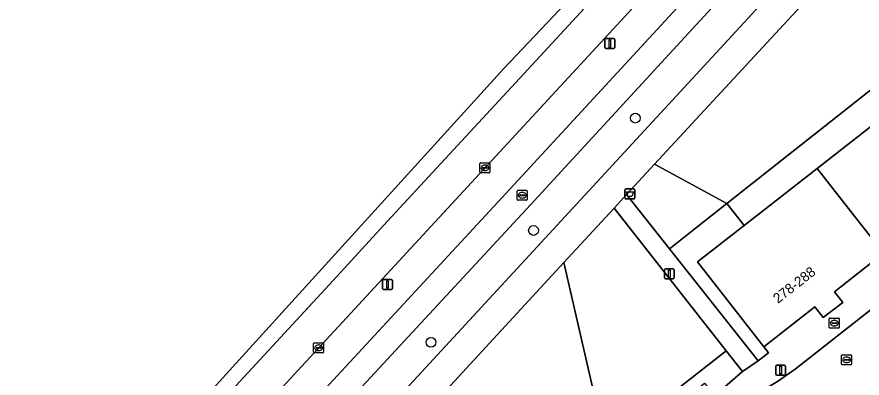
# Model space of a CAD drawing. Extents: x 159217 to 160349, y 381246 to 382172.
# Drawn here: x 159660.9 to 159745.5, y 381709.6 to 381745.8 of the extents above; entities that cross this region are included whole.
import ezdxf

# ---------------------------------------------------------------- set-up
doc = ezdxf.new("R2010")
doc.units = 0
for name, color, linetype in [('IMGEO_Afvalbak', 7, 'Continuous'), ('IMGEO_Berm_groen', 7, 'Continuous'), ('IMGEO_Boom', 7, 'Continuous'), ('IMGEO_Brandkraan', 7, 'Continuous'), ('IMGEO_Fietspad_gesloten', 7, 'Continuous'), ('IMGEO_Groenvoorziening', 7, 'Continuous'), ('IMGEO_Haag', 7, 'Continuous'), ('IMGEO_Kolk', 7, 'Continuous'), ('IMGEO_Lichtmast', 7, 'Continuous'), ('IMGEO_Pand', 7, 'Continuous'), ('IMGEO_Pand_nummerreeks', 7, 'Continuous'), ('IMGEO_Rijbaan_lokaal_open', 7, 'Continuous'), ('IMGEO_Rijbaan_regionaal_gesloten', 7, 'Continuous'), ('IMGEO_Rioolput', 7, 'Continuous'), ('IMGEO_Voetpad_open', 7, 'Continuous')]:
    doc.layers.add(name, color=color, linetype=linetype)

msp = doc.modelspace()

# ---------------------------------------------------------------- linework, layer by layer
at = {"layer": 'IMGEO_Afvalbak'}
for p, q in [((159721.722, 381727.669), (159721.722, 381728.469)), ((159721.722, 381728.469), (159721.722, 381727.669)), ((159721.822, 381728.569), (159722.612, 381728.569)), ((159722.612, 381728.569), (159721.822, 381728.569)), ((159722.712, 381728.469), (159722.712, 381727.669)), ((159722.712, 381727.669), (159722.712, 381728.469)), ((159722.612, 381727.569), (159721.822, 381727.569)), ((159721.822, 381727.569), (159722.612, 381727.569))]:
    msp.add_line(p, q, dxfattribs=at)
msp.add_lwpolyline([(159721.865, 381728.283), (159722.569, 381728.283), (159722.42, 381727.813), (159722.014, 381727.813), (159721.865, 381728.283)], dxfattribs=at)
for centre, start, end in [((159721.822, 381728.469), 90, 180), ((159721.822, 381728.469), 90, 180), ((159722.612, 381728.469), 0, 90), ((159722.612, 381728.469), 360, 90), ((159721.822, 381727.669), 180, 270), ((159721.822, 381727.669), 180, 270), ((159722.612, 381727.669), 270, 0), ((159722.612, 381727.669), 270, 0)]:
    msp.add_arc(centre, 0.1, start, end, dxfattribs=at)
at = {"layer": 'IMGEO_Berm_groen'}
msp.add_lwpolyline([(159853.494, 381886.181), (159852.47, 381885.258), (159842.203, 381875.059), (159835.047, 381867.74), (159825.175, 381857.422), (159808.382, 381839.524), (159762.299, 381789.78), (159757.702, 381784.817), (159640.048, 381657.48), (159637.399, 381654.559), (159636.301, 381652.991), (159629.478, 381641.885), (159628.555, 381640.744), (159629.543, 381639.855), (159629.68, 381639.699), (159634.406, 381645.8), (159639.364, 381651.824), (159643.967, 381657.085), (159662.078, 381676.527), (159710.236, 381728.578), (159764.638, 381787.591)], dxfattribs=at)
at = {"layer": 'IMGEO_Boom'}
for centre in [(159722.763, 381735.66), (159712.574, 381724.417), (159702.303, 381713.224)]:
    msp.add_circle(centre, 0.489, dxfattribs=at)
at = {"layer": 'IMGEO_Brandkraan'}
for p, q in [((159742.178, 381714.715), (159742.178, 381715.567)), ((159742.253, 381715.641), (159743.105, 381715.641)), ((159742.666, 381715.421), (159742.691, 381715.421)), ((159743.179, 381715.567), (159743.179, 381714.715)), ((159743.105, 381714.641), (159742.253, 381714.641)), ((159742.437, 381715.135), (159742.437, 381715.147)), ((159742.875, 381715.098), (159742.477, 381715.098)), ((159742.48, 381715.184), (159742.878, 381715.184)), ((159742.689, 381714.861), (159742.664, 381714.861)), ((159742.921, 381715.147), (159742.921, 381715.135))]:
    msp.add_line(p, q, dxfattribs=at)
for points in [[(159742.178, 381714.715), (159742.178, 381715.567)], [(159742.253, 381715.641), (159743.105, 381715.641)], [(159743.179, 381715.567), (159743.179, 381714.715)], [(159743.105, 381714.641), (159742.253, 381714.641)]]:
    msp.add_lwpolyline(points, dxfattribs=at)
for centre, radius, start, end in [((159742.255, 381715.565), 0.0765, 91.55205, 178.44795), ((159742.255, 381715.565), 0.0765, 91.55205, 178.44795), ((159743.103, 381715.565), 0.0765, 1.55205, 88.44795), ((159743.103, 381715.565), 0.0765, 1.55205, 88.44795), ((159742.255, 381714.717), 0.0765, 181.55205, 268.44795), ((159742.255, 381714.717), 0.0765, 181.55205, 268.44795), ((159742.477, 381715.144), 0.0403, 85.87752, 175.75265), ((159742.474, 381715.134), 0.0366, 178.93798, 274.71019), ((159742.878, 381715.141), 0.043, 264.86636, 352.45326), ((159742.882, 381715.146), 0.0386, 1.73085, 96.63898), ((159743.103, 381714.717), 0.0765, 271.55205, 358.44795), ((159743.103, 381714.717), 0.0765, 271.55205, 358.44795)]:
    msp.add_arc(centre, radius, start, end, dxfattribs=at)
for centre, major_axis, ratio, start_param, end_param in [((159742.665, 381715.141), (-0.387, 0.002), 0.722429, 4.712389, 7.853982), ((159742.69, 381715.141), (-0.39, 0.002), 0.717154, 1.570796, 4.712389)]:
    msp.add_ellipse(centre, major_axis=major_axis, ratio=ratio, start_param=start_param, end_param=end_param, dxfattribs=at)
at = {"layer": 'IMGEO_Fietspad_gesloten'}
for points in [[(159712.278, 381726.997), (159749.294, 381767.255), (159766.48, 381785.868), (159764.638, 381787.591), (159710.236, 381728.578), (159662.078, 381676.527), (159643.967, 381657.085), (159639.364, 381651.824), (159634.406, 381645.8), (159629.68, 381639.699), (159613.744, 381622.115), (159607.679, 381616.725)], [(159600.194, 381609.412), (159602.096, 381607.781), (159605.72, 381611.514), (159609.864, 381615.275), (159613.837, 381619.072), (159627.95, 381634.279), (159632.567, 381639.362), (159637.494, 381645.52), (159642.695, 381651.795), (159649.844, 381659.632), (159712.278, 381726.997)]]:
    msp.add_lwpolyline(points, dxfattribs=at)
at = {"layer": 'IMGEO_Groenvoorziening'}
for points in [[(159738.017, 381750), (159768.968, 381783.54), (159766.874, 381785.5), (159766.48, 381785.868), (159749.294, 381767.255), (159712.278, 381726.997), (159649.844, 381659.632), (159642.695, 381651.795), (159637.494, 381645.52), (159632.567, 381639.362), (159627.95, 381634.279), (159629.643, 381632.69), (159653.897, 381658.843)], [(159731.935, 381727.131), (159760.899, 381750), (159770.053, 381757.228), (159766.379, 381776.207), (159742.186, 381750), (159724.688, 381731.045)], [(159770.053, 381757.228), (159760.899, 381750), (159731.935, 381727.131), (159733.665, 381724.918), (159740.974, 381730.631), (159752.784, 381739.863), (159764.59, 381749.091), (159765.753, 381750), (159774.065, 381756.497)], [(159726.192, 381722.565), (159731.935, 381727.131), (159724.688, 381731.045), (159721.887, 381728.002)], [(159731.871, 381712.36), (159720.635, 381726.662), (159715.613, 381721.211), (159719.818, 381702.922)], [(159726.192, 381722.565), (159735.063, 381711.362), (159736.098, 381712.17), (159735.632, 381712.764), (159728.993, 381721.266), (159733.665, 381724.918), (159731.935, 381727.131)], [(159719.818, 381702.922), (159715.613, 381721.211), (159674.596, 381676.692), (159680.577, 381672.195)], [(159719.818, 381702.922), (159720.432, 381700.252), (159682.88, 381670.464), (159680.577, 381672.195), (159675.736, 381668.404), (159684.834, 381656.905), (159685.759, 381657.626), (159685.188, 381658.413), (159678.59, 381666.838), (159690.401, 381676.084), (159702.212, 381685.331), (159714.024, 381694.577), (159726.022, 381703.97), (159727.091, 381704.807), (159725.977, 381706.23), (159729.692, 381709.139), (159730.684, 381707.872), (159733.499, 381710.288), (159731.871, 381712.36)]]:
    msp.add_lwpolyline(points, close=True, dxfattribs=at)
at = {"layer": 'IMGEO_Haag'}
for points in [[(159768.968, 381783.54), (159766.874, 381785.5), (159766.48, 381785.868), (159749.294, 381767.255), (159712.278, 381726.997), (159649.844, 381659.632), (159642.695, 381651.795), (159637.494, 381645.52), (159632.567, 381639.362), (159627.95, 381634.279), (159629.643, 381632.69), (159653.897, 381658.843), (159738.017, 381750)], [(159726.192, 381722.565), (159735.063, 381711.362), (159736.098, 381712.17), (159735.632, 381712.764), (159728.993, 381721.266), (159733.665, 381724.918), (159731.935, 381727.131)], [(159719.818, 381702.922), (159720.432, 381700.252), (159682.88, 381670.464), (159680.577, 381672.195), (159675.736, 381668.404), (159684.834, 381656.905), (159685.759, 381657.626), (159685.188, 381658.413), (159678.59, 381666.838), (159690.401, 381676.084), (159702.212, 381685.331), (159714.024, 381694.577), (159726.022, 381703.97), (159727.091, 381704.807), (159725.977, 381706.23), (159729.692, 381709.139), (159730.684, 381707.872), (159733.499, 381710.288), (159731.871, 381712.36)]]:
    msp.add_lwpolyline(points, close=True, dxfattribs=at)
at = {"layer": 'IMGEO_Kolk'}
for p, q in [((159707.206, 381730.258), (159707.206, 381731.11)), ((159707.281, 381731.184), (159708.133, 381731.184)), ((159707.465, 381730.678), (159707.465, 381730.69)), ((159707.903, 381730.641), (159707.505, 381730.641)), ((159707.508, 381730.727), (159707.906, 381730.727)), ((159707.694, 381730.964), (159707.719, 381730.964)), ((159707.949, 381730.69), (159707.949, 381730.678)), ((159708.207, 381731.11), (159708.207, 381730.258)), ((159708.133, 381730.184), (159707.281, 381730.184)), ((159707.717, 381730.404), (159707.692, 381730.404)), ((159690.561, 381712.245), (159690.561, 381713.097)), ((159690.636, 381713.171), (159691.488, 381713.171)), ((159691.049, 381712.951), (159691.074, 381712.951)), ((159691.562, 381713.097), (159691.562, 381712.245)), ((159691.488, 381712.171), (159690.636, 381712.171)), ((159690.82, 381712.665), (159690.82, 381712.677)), ((159691.258, 381712.628), (159690.86, 381712.628)), ((159690.863, 381712.714), (159691.261, 381712.714)), ((159691.072, 381712.391), (159691.047, 381712.391)), ((159691.304, 381712.677), (159691.304, 381712.665))]:
    msp.add_line(p, q, dxfattribs=at)
for points in [[(159707.206, 381730.258), (159707.206, 381731.11)], [(159707.281, 381731.184), (159708.133, 381731.184)], [(159708.207, 381731.11), (159708.207, 381730.258)], [(159708.133, 381730.184), (159707.281, 381730.184)], [(159690.561, 381712.245), (159690.561, 381713.097)], [(159690.636, 381713.171), (159691.488, 381713.171)], [(159691.562, 381713.097), (159691.562, 381712.245)], [(159691.488, 381712.171), (159690.636, 381712.171)]]:
    msp.add_lwpolyline(points, dxfattribs=at)
for centre, radius, start, end in [((159707.283, 381731.108), 0.0765, 91.55205, 178.44795), ((159707.283, 381731.108), 0.0765, 91.55205, 178.44795), ((159707.505, 381730.687), 0.0403, 85.87752, 175.75265), ((159707.502, 381730.677), 0.0366, 178.93798, 274.71019), ((159707.906, 381730.684), 0.043, 264.86636, 352.45326), ((159707.91, 381730.689), 0.0386, 1.73085, 96.63898), ((159708.131, 381731.108), 0.0765, 1.55205, 88.44795), ((159708.131, 381731.108), 0.0765, 1.55205, 88.44795), ((159707.283, 381730.26), 0.0765, 181.55205, 268.44795), ((159707.283, 381730.26), 0.0765, 181.55205, 268.44795), ((159708.131, 381730.26), 0.0765, 271.55205, 358.44795), ((159708.131, 381730.26), 0.0765, 271.55205, 358.44795), ((159690.638, 381713.095), 0.0765, 91.55205, 178.44795), ((159690.638, 381713.095), 0.0765, 91.55205, 178.44795), ((159691.486, 381713.095), 0.0765, 1.55205, 88.44795), ((159691.486, 381713.095), 0.0765, 1.55205, 88.44795), ((159690.638, 381712.247), 0.0765, 181.55205, 268.44795), ((159690.638, 381712.247), 0.0765, 181.55205, 268.44795), ((159690.86, 381712.674), 0.0403, 85.87752, 175.75265), ((159690.857, 381712.664), 0.0366, 178.93798, 274.71019), ((159691.261, 381712.671), 0.043, 264.86636, 352.45326), ((159691.265, 381712.676), 0.0386, 1.73085, 96.63898), ((159691.486, 381712.247), 0.0765, 271.55205, 358.44795), ((159691.486, 381712.247), 0.0765, 271.55205, 358.44795)]:
    msp.add_arc(centre, radius, start, end, dxfattribs=at)
for centre, major_axis, ratio, start_param, end_param in [((159707.693, 381730.684), (-0.387, 0.002), 0.722429, 4.712389, 7.853982), ((159707.718, 381730.684), (-0.39, 0.002), 0.717154, 1.570796, 4.712389), ((159691.048, 381712.671), (-0.387, 0.002), 0.722429, 4.712389, 7.853982), ((159691.073, 381712.671), (-0.39, 0.002), 0.717154, 1.570796, 4.712389)]:
    msp.add_ellipse(centre, major_axis=major_axis, ratio=ratio, start_param=start_param, end_param=end_param, dxfattribs=at)
at = {"layer": 'IMGEO_Lichtmast'}
for p, q in [((159719.722, 381742.723), (159719.722, 381743.523)), ((159719.722, 381743.523), (159719.722, 381742.723)), ((159719.822, 381743.623), (159720.612, 381743.623)), ((159720.612, 381743.623), (159719.822, 381743.623)), ((159720.712, 381743.523), (159720.712, 381742.723)), ((159720.712, 381742.723), (159720.712, 381743.523)), ((159720.612, 381742.623), (159719.822, 381742.623)), ((159719.822, 381742.623), (159720.612, 381742.623)), ((159725.774, 381720.572), (159726.564, 381720.572)), ((159726.564, 381720.572), (159725.774, 381720.572)), ((159725.674, 381719.672), (159725.674, 381720.472)), ((159725.674, 381720.472), (159725.674, 381719.672)), ((159726.664, 381720.472), (159726.664, 381719.672)), ((159726.664, 381719.672), (159726.664, 381720.472)), ((159697.461, 381718.615), (159697.461, 381719.415)), ((159697.461, 381719.415), (159697.461, 381718.615)), ((159697.561, 381719.515), (159698.351, 381719.515)), ((159698.351, 381719.515), (159697.561, 381719.515)), ((159698.451, 381719.415), (159698.451, 381718.615)), ((159698.451, 381718.615), (159698.451, 381719.415)), ((159726.564, 381719.572), (159725.774, 381719.572)), ((159725.774, 381719.572), (159726.564, 381719.572)), ((159698.351, 381718.515), (159697.561, 381718.515)), ((159697.561, 381718.515), (159698.351, 381718.515)), ((159736.817, 381710.042), (159736.817, 381710.842)), ((159736.817, 381710.842), (159736.817, 381710.042)), ((159736.917, 381710.942), (159737.707, 381710.942)), ((159737.707, 381710.942), (159736.917, 381710.942)), ((159737.807, 381710.842), (159737.807, 381710.042)), ((159737.807, 381710.042), (159737.807, 381710.842)), ((159737.707, 381709.942), (159736.917, 381709.942)), ((159736.917, 381709.942), (159737.707, 381709.942))]:
    msp.add_line(p, q, dxfattribs=at)
for points in [[(159720.142, 381743.498), (159720.292, 381743.498), (159720.292, 381742.748), (159720.142, 381742.748), (159720.142, 381743.498)], [(159726.094, 381720.447), (159726.244, 381720.447), (159726.244, 381719.697), (159726.094, 381719.697), (159726.094, 381720.447)], [(159697.881, 381719.39), (159698.031, 381719.39), (159698.031, 381718.64), (159697.881, 381718.64), (159697.881, 381719.39)], [(159737.237, 381710.817), (159737.387, 381710.817), (159737.387, 381710.067), (159737.237, 381710.067), (159737.237, 381710.817)]]:
    msp.add_lwpolyline(points, dxfattribs=at)
for centre, start, end in [((159719.822, 381743.523), 90, 180), ((159719.822, 381743.523), 90, 180), ((159720.612, 381743.523), 0, 90), ((159720.612, 381743.523), 360, 90), ((159719.822, 381742.723), 180, 270), ((159719.822, 381742.723), 180, 270), ((159720.612, 381742.723), 270, 0), ((159720.612, 381742.723), 270, 0), ((159725.774, 381720.472), 90, 180), ((159725.774, 381720.472), 90, 180), ((159726.564, 381720.472), 0, 90), ((159726.564, 381720.472), 360, 90), ((159725.774, 381719.672), 180, 270), ((159725.774, 381719.672), 180, 270), ((159726.564, 381719.672), 270, 0), ((159726.564, 381719.672), 270, 0), ((159697.561, 381719.415), 90, 180), ((159697.561, 381719.415), 90, 180), ((159698.351, 381719.415), 0, 90), ((159698.351, 381719.415), 360, 90), ((159697.561, 381718.615), 180, 270), ((159697.561, 381718.615), 180, 270), ((159698.351, 381718.615), 270, 0), ((159698.351, 381718.615), 270, 0), ((159736.917, 381710.842), 90, 180), ((159736.917, 381710.842), 90, 180), ((159737.707, 381710.842), 0, 90), ((159737.707, 381710.842), 360, 90), ((159736.917, 381710.042), 180, 270), ((159736.917, 381710.042), 180, 270), ((159737.707, 381710.042), 270, 0), ((159737.707, 381710.042), 270, 0)]:
    msp.add_arc(centre, 0.1, start, end, dxfattribs=at)
at = {"layer": 'IMGEO_Pand'}
for points in [[(159759.437, 381731.352), (159752.784, 381739.863), (159740.974, 381730.631), (159747.622, 381722.127), (159752.552, 381725.976), (159753.383, 381724.912), (159755.33, 381726.432), (159754.499, 381727.496)], [(159740.974, 381730.631), (159733.665, 381724.918), (159728.993, 381721.266), (159735.632, 381712.764), (159740.745, 381716.757), (159741.576, 381715.693), (159743.523, 381717.213), (159742.692, 381718.277), (159747.622, 381722.127)]]:
    msp.add_lwpolyline(points, close=True, dxfattribs=at)
at = {"layer": 'IMGEO_Rijbaan_lokaal_open'}
msp.add_lwpolyline([(159775.451, 381739.376), (159738.75, 381710.527), (159736.985, 381709.283), (159734.439, 381707.77), (159731.768, 381706.49), (159733.528, 381704.259), (159735.419, 381701.861), (159737.311, 381699.462), (159739.202, 381697.064), (159741.094, 381694.666), (159747.688, 381700.089)], dxfattribs=at)
at = {"layer": 'IMGEO_Rijbaan_regionaal_gesloten'}
for points in [[(159849.958, 381887.692), (159840.8, 381878.514), (159830.13, 381867.652), (159822.889, 381860.084), (159814.994, 381851.76), (159810.756, 381847.255), (159802.521, 381838.469), (159791.265, 381826.348), (159777.035, 381810.935), (159760.686, 381793.237), (159749.78, 381781.446), (159741.608, 381772.601), (159711.603, 381740.093), (159697.924, 381725.313), (159692.515, 381719.406), (159673.411, 381698.738), (159662.487, 381686.935), (159632.439, 381654.477)], [(159640.048, 381657.48), (159757.702, 381784.817), (159762.299, 381789.78), (159808.382, 381839.524), (159825.175, 381857.422), (159835.047, 381867.74), (159842.203, 381875.059), (159852.47, 381885.258)], [(159632.439, 381654.477), (159662.487, 381686.935), (159673.411, 381698.738), (159692.515, 381719.406), (159697.924, 381725.313), (159711.603, 381740.093), (159741.608, 381772.601), (159749.78, 381781.446), (159760.686, 381793.237), (159777.035, 381810.935), (159791.265, 381826.348), (159802.521, 381838.469), (159810.756, 381847.255), (159814.994, 381851.76), (159709.596, 381740.644), (159571.505, 381588.644)]]:
    msp.add_lwpolyline(points, dxfattribs=at)
at = {"layer": 'IMGEO_Rioolput'}
for p, q in [((159710.939, 381727.513), (159710.939, 381728.365)), ((159711.014, 381728.439), (159711.866, 381728.439)), ((159711.427, 381728.219), (159711.452, 381728.219)), ((159711.94, 381728.365), (159711.94, 381727.513)), ((159711.866, 381727.439), (159711.014, 381727.439)), ((159711.198, 381727.933), (159711.198, 381727.945)), ((159711.636, 381727.896), (159711.238, 381727.896)), ((159711.241, 381727.982), (159711.639, 381727.982)), ((159711.45, 381727.659), (159711.425, 381727.659)), ((159711.682, 381727.945), (159711.682, 381727.933)), ((159743.416, 381711.041), (159743.416, 381711.893)), ((159743.491, 381711.967), (159744.343, 381711.967)), ((159743.675, 381711.461), (159743.675, 381711.473)), ((159744.113, 381711.424), (159743.715, 381711.424)), ((159743.718, 381711.51), (159744.116, 381711.51)), ((159743.927, 381711.187), (159743.902, 381711.187)), ((159743.904, 381711.747), (159743.929, 381711.747)), ((159744.159, 381711.473), (159744.159, 381711.461)), ((159744.417, 381711.893), (159744.417, 381711.041)), ((159744.343, 381710.967), (159743.491, 381710.967))]:
    msp.add_line(p, q, dxfattribs=at)
for points in [[(159710.939, 381727.513), (159710.939, 381728.365)], [(159711.014, 381728.439), (159711.866, 381728.439)], [(159711.94, 381728.365), (159711.94, 381727.513)], [(159711.866, 381727.439), (159711.014, 381727.439)], [(159743.416, 381711.041), (159743.416, 381711.893)], [(159743.491, 381711.967), (159744.343, 381711.967)], [(159744.417, 381711.893), (159744.417, 381711.041)], [(159744.343, 381710.967), (159743.491, 381710.967)]]:
    msp.add_lwpolyline(points, dxfattribs=at)
for centre, radius, start, end in [((159711.016, 381728.363), 0.0765, 91.55205, 178.44795), ((159711.016, 381728.363), 0.0765, 91.55205, 178.44795), ((159711.864, 381728.363), 0.0765, 1.55205, 88.44795), ((159711.864, 381728.363), 0.0765, 1.55205, 88.44795), ((159711.016, 381727.515), 0.0765, 181.55205, 268.44795), ((159711.016, 381727.515), 0.0765, 181.55205, 268.44795), ((159711.238, 381727.942), 0.0403, 85.87752, 175.75265), ((159711.235, 381727.932), 0.0366, 178.93798, 274.71019), ((159711.639, 381727.939), 0.043, 264.86636, 352.45326), ((159711.643, 381727.944), 0.0386, 1.73085, 96.63898), ((159711.864, 381727.515), 0.0765, 271.55205, 358.44795), ((159711.864, 381727.515), 0.0765, 271.55205, 358.44795), ((159743.493, 381711.891), 0.0765, 91.55205, 178.44795), ((159743.493, 381711.891), 0.0765, 91.55205, 178.44795), ((159743.715, 381711.47), 0.0403, 85.87752, 175.75265), ((159743.712, 381711.46), 0.0366, 178.93798, 274.71019), ((159744.116, 381711.467), 0.043, 264.86636, 352.45326), ((159744.12, 381711.472), 0.0386, 1.73085, 96.63898), ((159744.341, 381711.891), 0.0765, 1.55205, 88.44795), ((159744.341, 381711.891), 0.0765, 1.55205, 88.44795), ((159743.493, 381711.043), 0.0765, 181.55205, 268.44795), ((159743.493, 381711.043), 0.0765, 181.55205, 268.44795), ((159744.341, 381711.043), 0.0765, 271.55205, 358.44795), ((159744.341, 381711.043), 0.0765, 271.55205, 358.44795)]:
    msp.add_arc(centre, radius, start, end, dxfattribs=at)
for centre, major_axis, ratio, start_param, end_param in [((159711.426, 381727.939), (-0.387, 0.002), 0.722429, 4.712389, 7.853982), ((159711.451, 381727.939), (-0.39, 0.002), 0.717154, 1.570796, 4.712389), ((159743.903, 381711.467), (-0.387, 0.002), 0.722429, 4.712389, 7.853982), ((159743.928, 381711.467), (-0.39, 0.002), 0.717154, 1.570796, 4.712389)]:
    msp.add_ellipse(centre, major_axis=major_axis, ratio=ratio, start_param=start_param, end_param=end_param, dxfattribs=at)
at = {"layer": 'IMGEO_Voetpad_open'}
for points in [[(159715.613, 381721.211), (159720.635, 381726.662), (159721.887, 381728.002), (159724.688, 381731.045), (159742.186, 381750), (159766.379, 381776.207), (159771.217, 381781.437), (159768.968, 381783.54), (159738.017, 381750), (159653.897, 381658.843), (159629.643, 381632.69), (159615.553, 381617.498), (159615.445, 381617.382), (159608.003, 381609.357), (159604.58, 381605.65), (159606.917, 381603.647), (159616.639, 381614.101), (159619.494, 381617.187), (159621.019, 381618.793), (159665.232, 381666.59), (159670.058, 381671.807), (159670.392, 381672.168), (159671.682, 381673.529), (159674.596, 381676.692)], [(159726.192, 381722.565), (159721.887, 381728.002), (159720.635, 381726.662), (159731.871, 381712.36), (159733.499, 381710.288), (159735.063, 381711.362)]]:
    msp.add_lwpolyline(points, close=True, dxfattribs=at)
msp.add_lwpolyline([(159747.622, 381722.127), (159742.692, 381718.277), (159743.523, 381717.213), (159741.576, 381715.693), (159740.745, 381716.757), (159735.632, 381712.764), (159736.098, 381712.17), (159735.063, 381711.362), (159733.499, 381710.288), (159730.684, 381707.872), (159731.636, 381706.657), (159731.768, 381706.49), (159734.439, 381707.77), (159736.985, 381709.283), (159738.75, 381710.527), (159775.451, 381739.376)], dxfattribs=at)

# ---------------------------------------------------------------- texts
at = {"layer": 'IMGEO_Pand_nummerreeks'}
msp.add_text('278-288', height=1, rotation=37.98482, dxfattribs=at).set_placement((159737.045, 381717.064))

doc.saveas('drawing.dxf')
